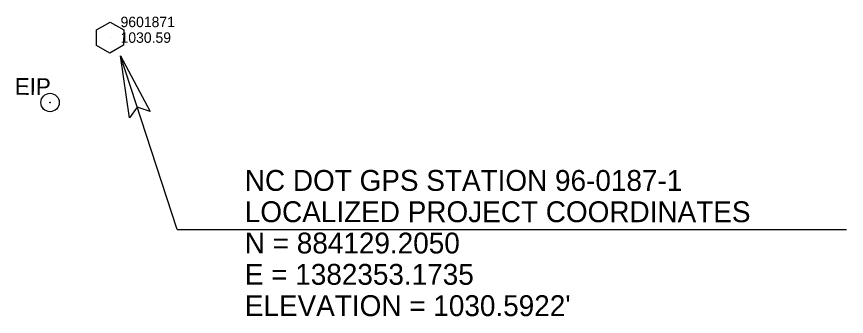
# Model space of a CAD drawing. Extents: x 1382088 to 1383563, y 883989 to 884716.
# Drawn here: x 1382330.8 to 1382529.5, y 884062.4 to 884134.2 of the extents above; entities that cross this region are included whole.
import ezdxf

# ---------------------------------------------------------------- set-up
doc = ezdxf.new("R2010")
doc.units = 0
for name, color, linetype in [('CTL GPS Vertical CELL', 7, 'Continuous'), ('CTL GPS Vertical Cogo Elevation', 7, 'Continuous'), ('CTL GPS Vertical Cogo Number', 7, 'Continuous'), ('CTL GPS Vertical Text', 7, 'Continuous'), ('Default', 7, 'Continuous'), ('Exist Property Iron Pin CELL', 7, 'Continuous'), ('Exist Property Iron Pin Text', 7, 'Continuous'), ('Old_Level_11', 7, 'Continuous')]:
    doc.layers.add(name, color=color, linetype=linetype)

msp = doc.modelspace()

# ---------------------------------------------------------------- linework, layer by layer
at = {"layer": 'CTL GPS Vertical CELL'}
msp.add_line((1382353.17, 884129.2), (1382353.17, 884129.2), dxfattribs=at)
msp.add_lwpolyline([(1382349.94, 884131.08), (1382353.19, 884132.89), (1382356.44, 884131.1), (1382356.39, 884127.38), (1382353.14, 884125.49), (1382349.94, 884127.3)], close=True, dxfattribs=at)
at = {"layer": 'Default'}
for q in [(1382355.65, 884124.81), (1382529.51, 884083.23)]:
    msp.add_line((1382369.2, 884083.23), q, dxfattribs=at)
at = {"layer": 'Exist Property Iron Pin CELL'}
for radius in [2.2, 0.0707]:
    msp.add_circle((1382338.79, 884113.66), radius, dxfattribs=at)
at = {"layer": 'Old_Level_11'}
msp.add_lwpolyline([(1382357.84, 884110.01), (1382355.65, 884124.81), (1382362.77, 884111.54), (1382359.69, 884112.51)], close=True, dxfattribs=at)

# ---------------------------------------------------------------- texts
at = {"layer": 'CTL GPS Vertical Cogo Elevation'}
msp.add_text('1030.59', height=2.5, dxfattribs=at).set_placement((1382355.67, 884127.96))
at = {"layer": 'CTL GPS Vertical Cogo Number'}
msp.add_text('9601871', height=2.5, dxfattribs=at).set_placement((1382355.67, 884131.71))
at = {"layer": 'CTL GPS Vertical Text'}
for s, p in [('NC DOT GPS STATION 96-0187-1', (1382385.43, 884092.5)), ('LOCALIZED PROJECT COORDINATES', (1382385.43, 884085)), ('N = 884129.2050', (1382385.43, 884077.5)), ('E = 1382353.1735', (1382385.43, 884070)), ("ELEVATION = 1030.5922'", (1382385.43, 884062.5))]:
    msp.add_text(s, height=5, rotation=359.9944, dxfattribs=at).set_placement(p)
at = {"layer": 'Exist Property Iron Pin Text'}
msp.add_text('EIP', height=4, rotation=359.7724, dxfattribs=at).set_placement((1382330.34, 884115.51))

doc.saveas('drawing.dxf')
